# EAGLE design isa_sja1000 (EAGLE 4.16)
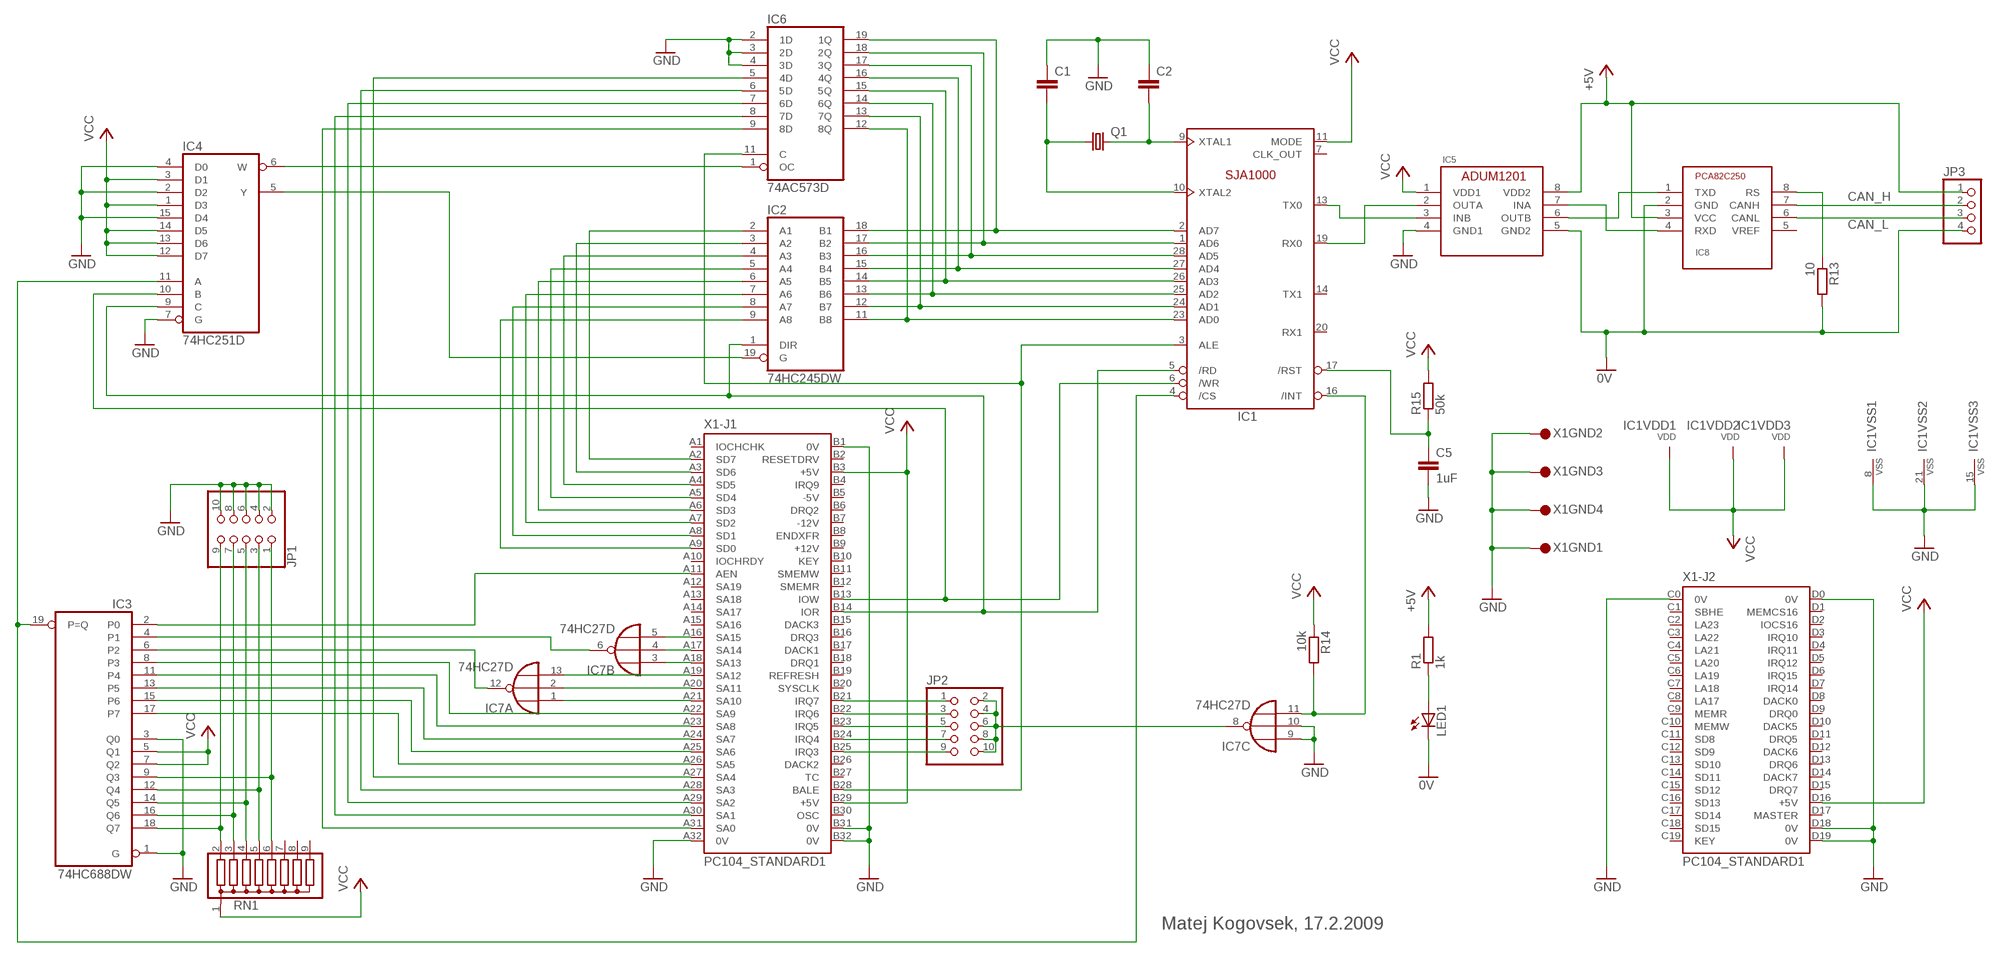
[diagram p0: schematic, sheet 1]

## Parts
C1  C-EUC0805  [C0805]
C2  C-EUC0805  [C0805]
C5  1uF  C-EUC1206  [C1206]
IC1  SJA1000T  [SO-28L]
IC2  74HC245DW  [SO20W]
IC3  74HC688DW  [SO20W]
IC4  74HC251D  [SO16]
IC5  ADUM1201  [SO08]
IC6  74AC573D  [SO20W]
IC7  74HC27D  [SO14]
IC8  MATEJ_PCA82C250  [MATEJ_SO8]
JP1  PINHD-2X5  [2X05]
JP2  PINHD-2X5  [2X05]
JP3  PINHD-1X4  [1X04]
LED1  LEDCHIPLED_1206  [CHIPLED_1206]
Q1  CRYSTALHC49S  [HC49/S]
R1  1k  R-EU_R1206  [R1206]
R13  10  R-EU_R1206  [R1206]
R14  10k  R-EU_R1206  [R1206]
R15  50k  R-EU_R1206  [R1206]
RN1  G08R  [SIL9]
X1  PC104_STANDARD1  [PC104-STANDARD]

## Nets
0V: IC5.5(GND2) IC8.2(GND) JP3.4 LED1.C R13.2
+5V: IC5.8(VDD2) IC8.3(VCC) JP3.1 R1.2
CAN_H: IC8.7(CANH) JP3.2
CAN_L: IC8.6(CANL) JP3.3
GND: C1.1 C2.1 C5.2 IC1.8(VSS) IC1.15(VSS) IC1.21(VSS) IC3.1(G) IC3.3(Q0) IC4.2(D2) IC4.4(D0) IC4.7(G) IC4.15(D4) IC5.4(GND1) IC6.2(1D) IC6.3(2D) IC6.4(3D) IC7.9(C:I0) IC7.10(C:I1) JP1.2 JP1.4 JP1.6 JP1.8 JP1.10 X1.A32(-J1:0V) X1.B1(-J1:0V) X1.B31(-J1:0V) X1.B32(-J1:0V) X1.C0(-J2:0V) X1.D0(-J2:0V) X1.D18(-J2:0V) X1.D19(-J2:0V) X1.GND@1 X1.GND@2 X1.GND@3 X1.GND@4
N$1: IC1.23(AD0) IC2.11(B8) IC6.12(8Q)
N$2: IC1.24(AD1) IC2.12(B7) IC6.13(7Q)
N$3: IC1.25(AD2) IC2.13(B6) IC6.14(6Q)
N$4: IC1.26(AD3) IC2.14(B5) IC6.15(5Q)
N$5: IC1.27(AD4) IC2.15(B4) IC6.16(4Q)
N$6: IC1.28(AD5) IC2.16(B3) IC6.17(3Q)
N$7: IC1.1(AD6) IC2.17(B2) IC6.18(2Q)
N$8: IC1.2(AD7) IC2.18(B1) IC6.19(1Q)
N$9: IC2.2(A1) X1.A2(-J1:SD7)
N$10: IC2.3(A2) X1.A3(-J1:SD6)
N$11: IC2.4(A3) X1.A4(-J1:SD5)
N$12: IC2.5(A4) X1.A5(-J1:SD4)
N$13: IC2.6(A5) X1.A6(-J1:SD3)
N$14: IC2.7(A6) X1.A7(-J1:SD2)
N$15: IC2.8(A7) X1.A8(-J1:SD1)
N$16: IC2.9(A8) X1.A9(-J1:SD0)
N$17: IC1.3(ALE) IC6.11(C) X1.B28(-J1:BALE)
N$18: IC1.6(/WR) IC4.10(B) X1.B13(-J1:IOW)
N$19: IC1.5(/RD) IC2.1(DIR) IC4.9(C) X1.B14(-J1:IOR)
N$20: IC3.11(P4) X1.A23(-J1:SA8)
N$21: IC7.1(A:I0) X1.A21(-J1:SA10)
N$22: IC6.9(8D) X1.A31(-J1:SA0)
N$23: IC6.8(7D) X1.A30(-J1:SA1)
N$24: IC6.7(6D) X1.A29(-J1:SA2)
N$25: IC6.6(5D) X1.A28(-J1:SA3)
N$26: IC6.5(4D) X1.A27(-J1:SA4)
N$27: IC3.17(P7) X1.A26(-J1:SA5)
N$28: IC3.15(P6) X1.A25(-J1:SA6)
N$29: IC3.13(P5) X1.A24(-J1:SA7)
N$30: IC2.19(G) IC4.5(Y)
N$31: IC4.6(W) IC6.1(OC)
N$32: IC3.8(P3) X1.A22(-J1:SA9)
N$33: JP2.9 X1.B25(-J1:IRQ3)
N$34: IC3.9(Q3) JP1.1 RN1.6
N$35: IC3.12(Q4) JP1.3 RN1.5
N$36: IC3.14(Q5) JP1.5 RN1.4
N$37: IC3.16(Q6) JP1.7 RN1.3
N$38: IC3.18(Q7) JP1.9 RN1.2
N$39: IC1.4(/CS) IC3.19(P=Q) IC4.11(A)
N$40: IC3.2(P0) X1.A11(-J1:AEN)
N$41: JP2.7 X1.B24(-J1:IRQ4)
N$42: JP2.5 X1.B23(-J1:IRQ5)
N$43: JP2.3 X1.B22(-J1:IRQ6)
N$44: JP2.1 X1.B21(-J1:IRQ7)
N$45: IC1.16(/INT) IC7.11(C:I2) R14.2
N$46: IC1.19(RX0) IC5.2(OUTA)
N$47: IC1.13(TX0) IC5.3(INB)
N$48: IC7.2(A:I1) X1.A20(-J1:SA11)
N$49: IC7.13(A:I2) X1.A19(-J1:SA12)
N$50: IC7.3(B:I0) X1.A18(-J1:SA13)
N$51: IC7.4(B:I1) X1.A17(-J1:SA14)
N$52: IC7.5(B:I2) X1.A16(-J1:SA15)
N$53: IC3.6(P2) IC7.12(A:O)
N$54: IC3.4(P1) IC7.6(B:O)
N$55: IC5.7(INA) IC8.4(RXD)
N$56: IC5.6(OUTB) IC8.1(TXD)
N$57: C5.1 IC1.17(/RST) R15.1
N$58: LED1.A R1.1
N$59: C1.2 IC1.10(XTAL2) Q1.1
N$60: C2.2 IC1.9(XTAL1) Q1.2
N$65: IC8.8(RS) R13.1
N$87: IC7.8(C:O) JP2.2 JP2.4 JP2.6 JP2.8 JP2.10
VCC: IC1.11(MODE) IC1.12(VDD) IC1.18(VDD) IC1.22(VDD) IC3.5(Q1) IC3.7(Q2) IC4.1(D3) IC4.3(D1) IC4.12(D7) IC4.13(D6) IC4.14(D5) IC5.1(VDD1) R14.1 R15.2 RN1.1 X1.B3(-J1:+5V) X1.B29(-J1:+5V) X1.D16(-J2:+5V)
Unconnected: IC1.7(CLK_OUT) IC1.14(TX1) IC1.20(RX1) IC8.5(VREF) RN1.7 RN1.8 RN1.9 X1.A1(-J1:IOCHCHK) X1.A10(-J1:IOCHRDY) X1.A12(-J1:SA19) X1.A13(-J1:SA18) X1.A14(-J1:SA17) X1.A15(-J1:SA16) X1.B2(-J1:RESETDRV) X1.B4(-J1:IRQ9) X1.B5(-J1:-5V) X1.B6(-J1:DRQ2) X1.B7(-J1:-12V) X1.B8(-J1:ENDXFR) X1.B9(-J1:+12V) X1.B10(-J1:KEY) X1.B11(-J1:SMEMW) X1.B12(-J1:SMEMR) X1.B15(-J1:DACK3) X1.B16(-J1:DRQ3) X1.B17(-J1:DACK1) X1.B18(-J1:DRQ1) X1.B19(-J1:REFRESH) X1.B20(-J1:SYSCLK) X1.B26(-J1:DACK2) X1.B27(-J1:TC) X1.B30(-J1:OSC) X1.C1(-J2:SBHE) X1.C2(-J2:LA23) X1.C3(-J2:LA22) X1.C4(-J2:LA21) X1.C5(-J2:LA20) X1.C6(-J2:LA19) X1.C7(-J2:LA18) X1.C8(-J2:LA17) X1.C9(-J2:MEMR) X1.C10(-J2:MEMW) X1.C11(-J2:SD8) X1.C12(-J2:SD9) X1.C13(-J2:SD10) X1.C14(-J2:SD11) X1.C15(-J2:SD12) X1.C16(-J2:SD13) X1.C17(-J2:SD14) X1.C18(-J2:SD15) X1.C19(-J2:KEY) X1.D1(-J2:MEMCS16) X1.D2(-J2:IOCS16) X1.D3(-J2:IRQ10) X1.D4(-J2:IRQ11) X1.D5(-J2:IRQ12) X1.D6(-J2:IRQ15) X1.D7(-J2:IRQ14) X1.D8(-J2:DACK0) X1.D9(-J2:DRQ0) X1.D10(-J2:DACK5) X1.D11(-J2:DRQ5) X1.D12(-J2:DACK6) X1.D13(-J2:DRQ6) X1.D14(-J2:DACK7) X1.D15(-J2:DRQ7) X1.D17(-J2:MASTER)

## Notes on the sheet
- SJA1000 | ADUM1201
- Matej Kogovsek, 17.2.2009

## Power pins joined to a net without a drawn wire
GND: IC2.10(GND) IC3.10(GND) IC4.8(GND) IC6.10(GND) IC7.7(P:GND)
VCC: IC2.20(VCC) IC3.20(VCC) IC4.16(VCC) IC6.20(VCC) IC7.14(P:VCC)

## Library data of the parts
C1 C2 C5 = rcl:C-EU: CAPACITOR, European symbol
IC1 = micro-philips:SJA1000: BASIC-CAN 2.0a Controller (former 82C200) Stand-alone CAN controller
IC2 = 74xx-eu:74*245: Octal BUS TRANSCEIVER, 3-state
IC3 = 74xx-eu:74*688: 8-bit MAGNITUDE/IDENTITY COMPARATOR, totem pole
IC4 = 74xx-eu:74*251: 1 of 8 data SELECTOR/MULTIPLEXER, 3-state
IC5 = matej_siwim:ADUM1201
IC6 = 74xx-eu:74*573: 8-bit D latch BUS DRIVER
IC7 = 74xx-eu:74*27: Triple 3-input NOR gate
IC8 = matej_siwim:MATEJ_PCA82C250: CAN controller interface
JP1 JP2 = pinhead:PINHD-2X5: PIN HEADER
JP3 = pinhead:PINHD-1X4: PIN HEADER
LED1 = led:LED: LED
Q1 = crystal:CRYSTAL: CRYSTAL
R1 R13-R15 = rcl:R-EU_: RESISTOR, European symbol
RN1 = resistor-sil:G08R: SIL RESISTOR
X1 = con-pc104:PC104_STANDARD: PC/104 Standard 16 bit

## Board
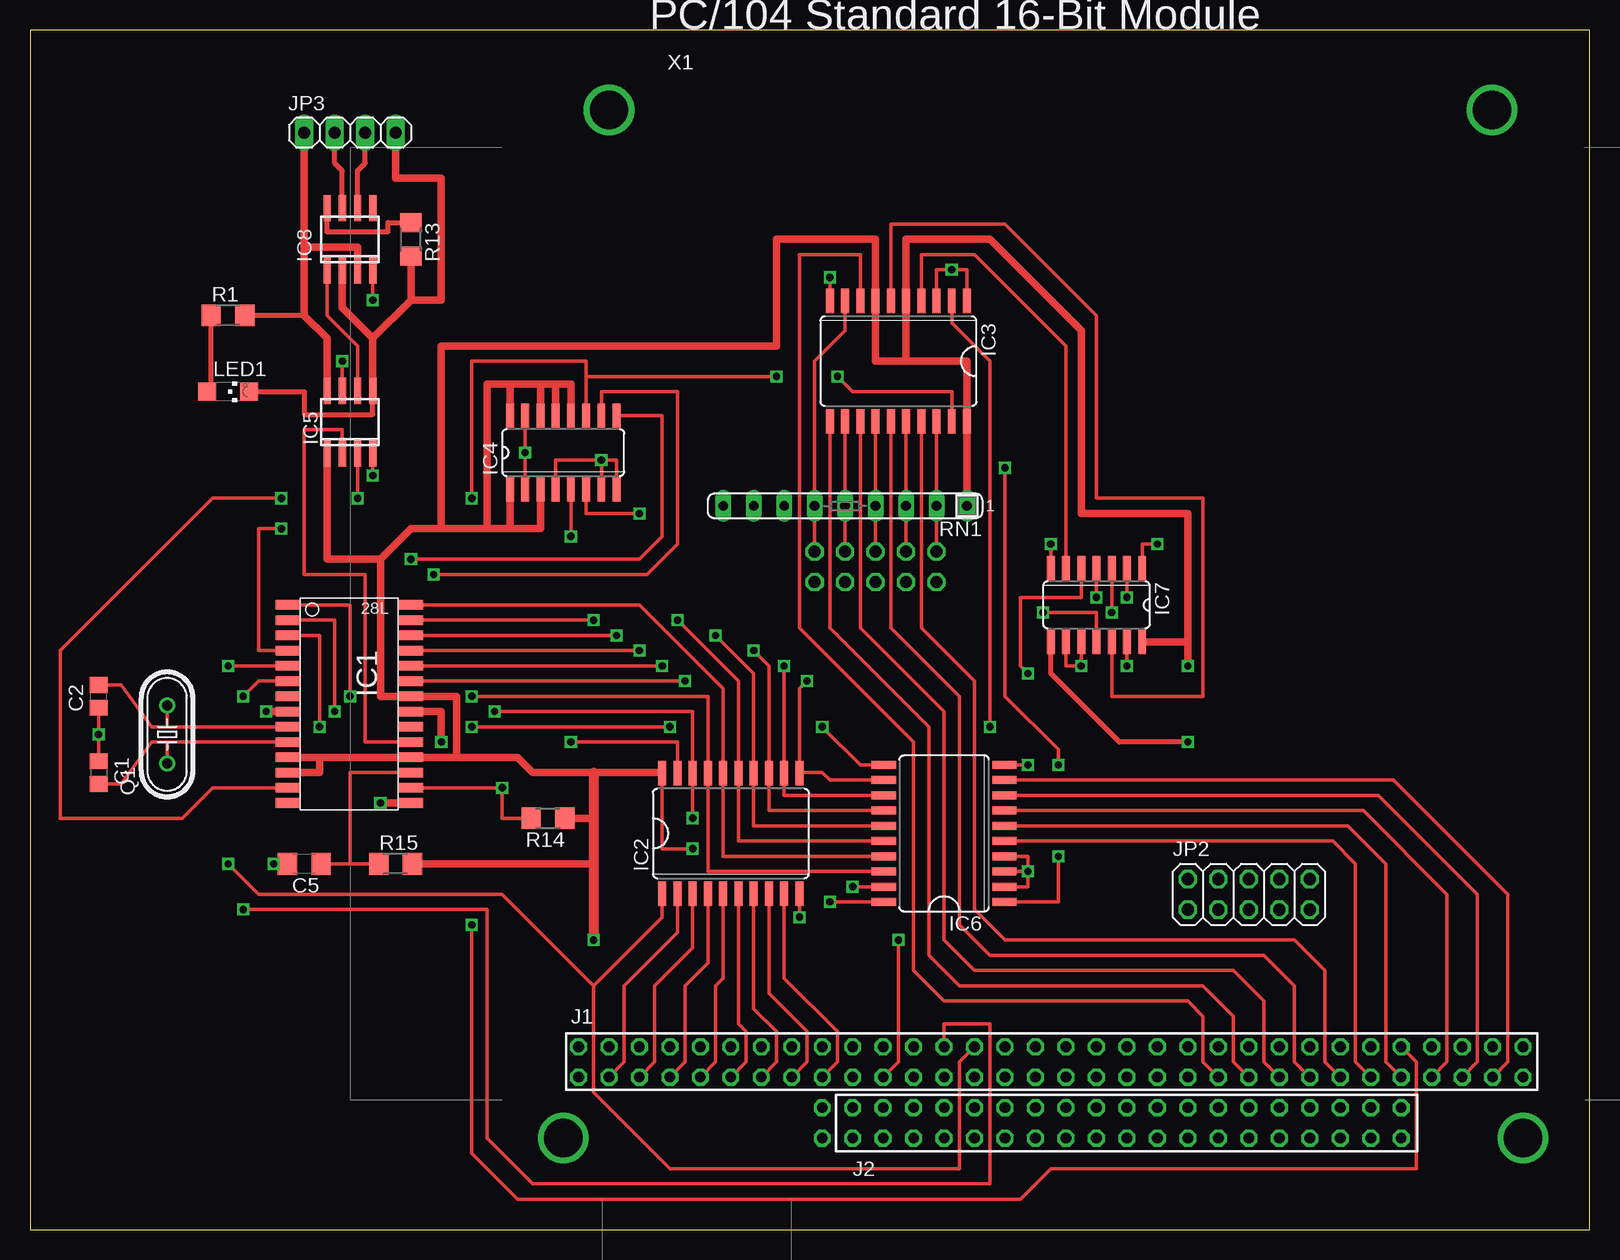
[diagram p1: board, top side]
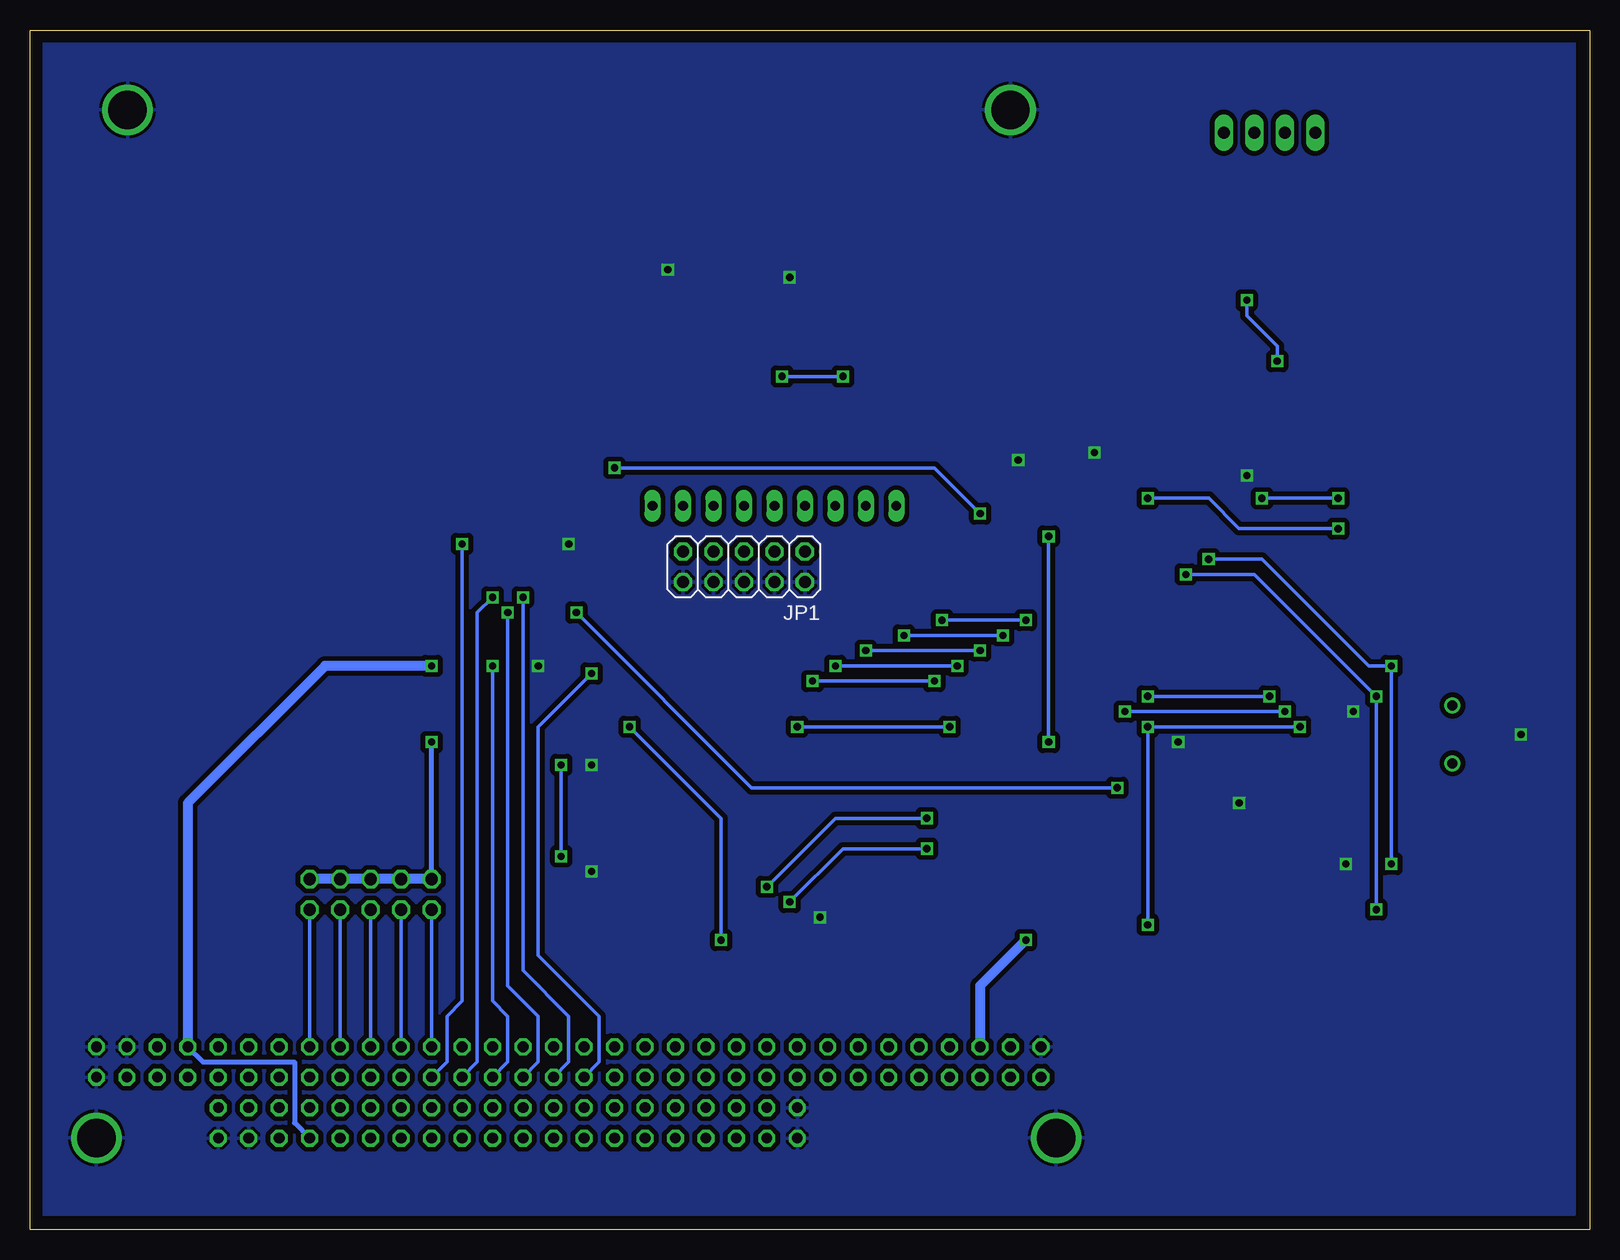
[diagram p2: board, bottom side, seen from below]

Size 130 x 100 mm. Coordinates in mm from the lower left corner, seen from the top.
Outline: 0,0 130,0 130,100 0,100 0,0
Copper layers (1*16): Top 0.035mm / dielectric 1.5mm / Bottom 0.035mm
Design rules "default": minimum track width 10mil, minimum drill 24mil, track to track 8mil, track to pad 8mil, pad to pad 8mil, via to via 8mil, smd to smd 8mil, copper to edge 40mil, drill to drill 8mil, minimum pad ring 10mil, minimum via ring 8mil, stop-mask expansion 4mil, vias tented up to drill 0mil, thermal gap 10mil

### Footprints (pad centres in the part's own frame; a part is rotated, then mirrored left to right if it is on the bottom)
C0805 = smd 1.3 x 1.5: 1 -0.95,0; 2 0.95,0
C1206 = smd 1.6 x 1.8: 1 -1.4,0; 2 1.4,0
SO-28L = smd 0.8 x 2: 1 -8.89,-5.207; 2 -7.62,-5.207; 3 -6.35,-5.207; 4 -5.08,-5.207; 5 -3.81,-5.207; 6 -2.54,-5.207; 7 -1.27,-5.207; 8 0,-5.207; 9 1.27,-5.207; 10 2.54,-5.207; 11 3.81,-5.207; 12 5.08,-5.207; 13 6.35,-5.207; 14 7.62,-5.207; 15 7.62,5.08; 16 6.35,5.08; 17 5.08,5.08; 18 3.81,5.08; 19 2.54,5.08; 20 1.27,5.08; 21 0,5.08; 22 -1.27,5.08; 23 -2.54,5.08; 24 -3.81,5.08; 25 -5.08,5.08; 26 -6.35,5.08; 27 -7.62,5.08; 28 -8.89,5.08
SO20W = smd 0.66 x 2.032: 1 -5.715,-5.029; 2 -4.445,-5.029; 3 -3.175,-5.029; 4 -1.905,-5.029; 5 -0.635,-5.029; 6 0.635,-5.029; 7 1.905,-5.029; 8 3.175,-5.029; 9 4.445,-5.029; 10 5.715,-5.029; 11 5.715,5.029; 12 4.445,5.029; 13 3.175,5.029; 14 1.905,5.029; 15 0.635,5.029; 16 -0.635,5.029; 17 -1.905,5.029; 18 -3.175,5.029; 19 -4.445,5.029; 20 -5.715,5.029
SO16 = smd 0.66 x 2.032: 1 -4.445,-3.073; 2 -3.175,-3.073; 3 -1.905,-3.073; 4 -0.635,-3.073; 5 0.635,-3.073; 6 1.905,-3.073; 7 3.175,-3.073; 8 4.445,-3.073; 9 4.445,3.073; 10 3.175,3.073; 11 1.905,3.073; 12 0.635,3.073; 13 -0.635,3.073; 14 -1.905,3.073; 15 -3.175,3.073; 16 -4.445,3.073
SO08@1 = smd 0.6 x 2.2: 1 -1.905,-2.6; 2 -0.635,-2.6; 3 0.635,-2.6; 4 1.905,-2.6; 5 1.905,2.6; 6 0.635,2.6; 7 -0.635,2.6; 8 -1.905,2.6
SO14 = smd 0.66 x 2.032: 1 -3.81,-3.073; 2 -2.54,-3.073; 3 -1.27,-3.073; 4 0,-3.073; 5 1.27,-3.073; 6 2.54,-3.073; 7 3.81,-3.073; 8 3.81,3.073; 9 2.54,3.073; 10 1.27,3.073; 11 0,3.073; 12 -1.27,3.073; 13 -2.54,3.073; 14 -3.81,3.073
MATEJ_SO8 = smd 0.6 x 2.2: 1 -1.905,-2.6; 2 -0.635,-2.6; 3 0.635,-2.6; 4 1.905,-2.6; 5 1.905,2.6; 6 0.635,2.6; 7 -0.635,2.6; 8 -1.905,2.6
2X05 = drill 1.016 octagon: 1 -5.08,-1.27; 2 -5.08,1.27; 3 -2.54,-1.27; 4 -2.54,1.27; 5 0,-1.27; 6 0,1.27; 7 2.54,-1.27; 8 2.54,1.27; 9 5.08,-1.27; 10 5.08,1.27
1X04 = drill 1.016 long: 1 -3.81,0; 2 -1.27,0; 3 1.27,0; 4 3.81,0
CHIPLED_1206 = smd 1.5 x 1.5: A 0,-1.75; C 0,1.75
HC49/S = drill 0.813 round: 1 -2.413,0; 2 2.413,0
R1206 = smd 1.6 x 1.8: 1 -1.4,0; 2 1.4,0
SIL9 = drill 0.813 long: 1 -10.16,0; 2 -7.62,0; 3 -5.08,0; 4 -2.54,0; 5 0,0; 6 2.54,0; 7 5.08,0; 8 7.62,0; 9 10.16,0
PC104-STANDARD = drill 0.9 pad 1.397 octagon: A1 6.35,10.16; A2 8.89,10.16; A3 11.43,10.16; A4 13.97,10.16; A5 16.51,10.16; A6 19.05,10.16; A7 21.59,10.16; A8 24.13,10.16; A9 26.67,10.16; A10 29.21,10.16; A11 31.75,10.16; A12 34.29,10.16; A13 36.83,10.16; A14 39.37,10.16; A15 41.91,10.16; A16 44.45,10.16; A17 46.99,10.16; A18 49.53,10.16; A19 52.07,10.16; A20 54.61,10.16; A21 57.15,10.16; A22 59.69,10.16; A23 62.23,10.16; A24 64.77,10.16; A25 67.31,10.16; A26 69.85,10.16; A27 72.39,10.16; A28 74.93,10.16; A29 77.47,10.16; A30 80.01,10.16; A31 82.55,10.16; A32 85.09,10.16; B1 6.35,12.7; B2 8.89,12.7; B3 11.43,12.7; B4 13.97,12.7; B5 16.51,12.7; B6 19.05,12.7; B7 21.59,12.7; B8 24.13,12.7; B9 26.67,12.7; B10 29.21,12.7; B11 31.75,12.7; B12 34.29,12.7; B13 36.83,12.7; B14 39.37,12.7; B15 41.91,12.7; B16 44.45,12.7; B17 46.99,12.7; B18 49.53,12.7; B19 52.07,12.7; B20 54.61,12.7; B21 57.15,12.7; B22 59.69,12.7; B23 62.23,12.7; B24 64.77,12.7; B25 67.31,12.7; B26 69.85,12.7; B27 72.39,12.7; B28 74.93,12.7; B29 77.47,12.7; B30 80.01,12.7; B31 82.55,12.7; B32 85.09,12.7; C0 26.67,7.62; C1 29.21,7.62; C2 31.75,7.62; C3 34.29,7.62; C4 36.83,7.62; C5 39.37,7.62; C6 41.91,7.62; C7 44.45,7.62; C8 46.99,7.62; C9 49.53,7.62; C10 52.07,7.62; C11 54.61,7.62; C12 57.15,7.62; C13 59.69,7.62; C14 62.23,7.62; C15 64.77,7.62; C16 67.31,7.62; C17 69.85,7.62; C18 72.39,7.62; C19 74.93,7.62; D0 26.67,5.08; D1 29.21,5.08; D2 31.75,5.08; D3 34.29,5.08; D4 36.83,5.08; D5 39.37,5.08; D6 41.91,5.08; D7 44.45,5.08; D8 46.99,5.08; D9 49.53,5.08; D10 52.07,5.08; D11 54.61,5.08; D12 57.15,5.08; D13 59.69,5.08; D14 62.23,5.08; D15 64.77,5.08; D16 67.31,5.08; D17 69.85,5.08; D18 72.39,5.08; D19 74.93,5.08 | drill 3.2 pad 4 round: GND@1 8.9,90.8; GND@2 82.5,90.8; GND@3 5.1,5.1; GND@4 85.1,5.1

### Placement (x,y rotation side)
C1  5.71,38.1 270 top
C2  5.71,44.45 90 top
C5  22.86,30.48 180 top
IC1  26.67,43.18 270 top
IC2  58.42,33.02 0 top
IC3  72.39,72.39 180 top
IC4  44.45,64.77 0 top
IC5  ADUM1201  [SO08@1]  26.67,67.31 0 top
IC6  76.2,33.02 90 top
IC7  88.9,52.07 180 top
IC8  26.67,82.55 0 top
JP1  70.48,55.24 180 bottom
JP2  101.6,27.94 0 top
JP3  26.67,91.44 0 top
LED1  16.51,69.85 270 top
Q1  11.43,41.27 90 top
R1  16.51,76.2 0 top
R13  31.75,82.55 270 top
R14  43.18,34.29 180 top
R15  30.48,30.48 0 top
RN1  67.94,60.33 180 top
X1  39.37,2.54 0 top

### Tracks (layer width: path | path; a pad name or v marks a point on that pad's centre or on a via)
0V
  Top 0.305: IC8.2 26.04,80.01
  Top 0.406: IC5.5 28.57,67.94 22.86,67.94 22.86,69.85 LED1.C
  Top 0.61: IC5.5 28.57,74.3 | 28.57,74.3 26.04,76.83 IC8.2 | 31.75,77.47 R13.2 | 28.57,74.3 31.75,77.47 | JP3.4 30.48,87.63 34.29,87.63 34.29,77.47 31.75,77.47
+5V
  Top 0.406: 22.86,76.2 R1.2
  Top 0.61: IC5.8 24.77,74.3 22.86,76.2 22.86,81.92 | 22.86,81.92 27.3,81.92 IC8.3 | 22.86,81.92 JP3.1
CAN_H
  Top 0.406: IC8.7 26.04,88.27 25.4,88.9 JP3.2
CAN_L
  Top 0.406: IC8.6 27.3,88.27 27.94,88.9 JP3.3
GND  (via drill 0.6)
  Top 0.305: v64.14,26.04 IC2.10 | IC4.15 v41.27,64.77 IC4.2 | IC4.8 48.9,64.14 v47.62,64.14 | v47.62,64.14 IC4.7 | IC4.4 43.81,64.14 v47.62,64.14 | C1.1 v5.71,41.27 C2.1 | IC7.9 86.36,46.99 v87.63,46.99 IC7.10 | IC7.7 v85.09,57.15 | IC6.2 83.19,28.57 v83.19,29.84 | IC6.4 83.19,31.11 v83.19,29.84 | IC6.3 v83.19,29.84 | IC6.10 v83.19,38.73 | IC3.3 75.56,80.01 v76.83,80.01 78.11,80.01 IC3.1 | IC3.10 v66.67,79.38 | v28.57,62.87 IC5.4 | 21.59,30.48 C5.2 v20.32,30.48
  Top 0.61: IC1.21 34.29,43.18 v34.29,40.64 | v29.21,35.56 IC1.15 | v19.68,43.18 IC1.8
  pour Bottom (isolate 0.406): 1.27,1.27 129.75,1.27 129.75,99.06 1.27,99.06
N$1  (via drill 0.6)
  Top 0.305: IC1.23 v54.61,45.72 | v64.77,45.72 64.14,45.09 IC2.11 64.14,38.1 66.04,38.1 66.67,37.47 IC6.12
  Bottom 0.305: v54.61,45.72 v64.77,45.72
N$2  (via drill 0.6)
  Top 0.305: IC1.24 v52.7,46.99 | v62.87,46.99 IC2.12 62.87,36.2 IC6.13
  Bottom 0.305: v52.7,46.99 v62.87,46.99
N$3  (via drill 0.6)
  Top 0.305: IC1.25 v50.8,48.26 | v60.33,48.26 61.59,46.99 IC2.13 61.59,34.92 IC6.14
  Bottom 0.305: v50.8,48.26 v60.33,48.26
N$4  (via drill 0.6)
  Top 0.305: IC1.26 v48.9,49.53 | v57.15,49.53 60.33,46.35 IC2.14 60.33,33.66 IC6.15
  Bottom 0.305: v48.9,49.53 v57.15,49.53
N$5  (via drill 0.6)
  Top 0.305: IC1.27 v46.99,50.8 | v53.98,50.8 59.05,45.72 IC2.15 59.05,32.38 IC6.16
  Bottom 0.305: v46.99,50.8 v53.98,50.8
N$6
  Top 0.305: IC1.28 50.8,52.07 57.78,45.09 IC2.16 57.78,31.11 IC6.17
N$7  (via drill 0.6)
  Top 0.305: IC6.18 56.52,29.84 IC2.17 56.52,44.45 v36.83,44.45 | IC1.1 26.67,52.07 v26.67,44.45
  Bottom 0.305: v26.67,44.45 v36.83,44.45
N$8  (via drill 0.6)
  Top 0.305: v68.58,28.57 IC6.19 | v55.24,34.29 IC2.18 55.24,43.18 v38.73,43.18 | IC1.2 25.4,50.8 v25.4,43.18
  Bottom 0.305: v68.58,28.57 62.87,34.29 v55.24,34.29 | v25.4,43.18 v38.73,43.18
N$9
  Top 0.305: IC2.2 53.98,24.77 49.53,20.32 49.53,13.97 X1.A2
N$10
  Top 0.305: X1.A3 52.07,13.97 52.07,20.32 55.24,23.5 IC2.3
N$11
  Top 0.305: IC2.4 56.52,22.23 54.61,20.32 54.61,13.97 X1.A4
N$12
  Top 0.305: IC2.5 57.78,20.95 57.15,20.32 57.15,13.97 X1.A5
N$13
  Top 0.305: IC2.6 59.05,17.14 59.69,16.51 59.69,13.97 X1.A6
N$14
  Top 0.305: IC2.7 60.33,18.41 62.23,16.51 62.23,13.97 X1.A7
N$15
  Top 0.305: IC2.8 61.59,19.68 64.77,16.51 64.77,13.97 X1.A8
N$16
  Top 0.305: IC2.9 62.87,20.95 67.31,16.51 67.31,13.97 X1.A9
N$17  (via drill 0.6)
  Top 0.305: IC1.3 24.13,49.53 v24.13,41.91 | v36.83,41.91 v53.34,41.91 | v66.04,41.91 69.22,38.73 IC6.11 | X1.B28 115.57,13.97 115.57,5.08 85.09,5.08 82.55,2.54 40.64,2.54 36.83,6.35 v36.83,25.4
  Bottom 0.305: v24.13,41.91 v36.83,41.91 v36.83,25.4 | v53.34,41.91 v66.04,41.91
N$18  (via drill 0.6)
  Top 0.305: X1.B13 76.2,17.14 80.01,17.14 80.01,3.81 41.91,3.81 38.1,7.62 38.1,26.67 v17.78,26.67 | v17.78,44.45 19.05,45.72 IC1.6 | IC4.10 47.62,69.85 53.98,69.85 53.98,57.15 51.44,54.61 v33.66,54.61
  Bottom 0.305: v17.78,26.67 v17.78,44.45 27.94,54.61 v33.66,54.61
N$19  (via drill 0.6)
  Top 0.305: X1.B14 77.47,13.97 77.47,5.08 53.34,5.08 46.99,11.43 46.99,20.32 | 46.99,20.32 52.7,26.04 IC2.1 | v16.51,46.99 IC1.5 | v16.51,30.48 19.05,27.94 39.37,27.94 46.99,20.32 | IC4.9 52.7,67.84 52.7,57.78 50.8,55.88 v31.75,55.88
  Bottom 0.305: v16.51,30.48 v16.51,46.99 18.41,46.99 27.3,55.88 v31.75,55.88
N$20
  Top 0.305: X1.A23 100.33,13.97 100.33,17.78 97.79,20.32 77.47,20.32 74.93,22.86 74.93,41.91 66.67,50.16 IC3.11
N$21  (via drill 0.6)
  Top 0.305: v93.98,57.15 92.71,57.15 IC7.1
  Bottom 0.305: X1.A21 95.25,13.97 95.25,17.78 93.98,19.05 v93.98,57.15
N$22
  Top 0.305: IC6.9 113.67,37.47 123.19,27.94 123.19,13.97 X1.A31
N$23
  Top 0.305: IC6.8 112.39,36.2 120.65,27.94 120.65,13.97 X1.A30
N$24
  Top 0.305: IC6.7 111.12,34.92 118.11,27.94 118.11,13.97 X1.A29
N$25
  Top 0.305: IC6.6 109.86,33.66 113.03,30.48 113.03,13.97 X1.A28
N$26
  Top 0.305: IC6.5 108.58,32.38 110.49,30.48 110.49,13.97 X1.A27
N$27
  Top 0.305: X1.A26 107.95,13.97 107.95,21.59 105.41,24.13 81.28,24.13 78.74,26.67 78.74,45.72 74.3,50.16 IC3.17
N$28
  Top 0.305: X1.A25 105.41,13.97 105.41,20.32 102.87,22.86 80.01,22.86 77.47,25.4 77.47,44.45 71.75,50.16 IC3.15
N$29
  Top 0.305: X1.A24 102.87,13.97 102.87,19.05 100.33,21.59 78.74,21.59 76.2,24.13 76.2,43.18 69.22,50.16 IC3.13
N$30  (via drill 0.6)
  Top 0.305: IC2.19 53.98,40.64 v45.09,40.64 | v45.09,57.78 IC4.5
  Bottom 0.305: v45.09,40.64 v45.09,57.78
N$31  (via drill 0.6)
  Top 0.305: IC6.1 85.72,27.3 v85.72,31.11 | v85.72,38.73 85.72,40.01 81.28,44.45 v81.28,63.5 | v50.8,59.69 46.35,59.69 IC4.6
  Bottom 0.305: v85.72,31.11 v85.72,38.73 | v81.28,63.5 54.61,63.5 v50.8,59.69
N$32
  Top 0.305: X1.A22 97.79,13.97 97.79,17.78 96.52,19.05 76.2,19.05 73.66,21.59 73.66,40.64 64.14,50.16 64.14,81.28 69.22,81.28 IC3.8
N$33
  Bottom 0.305: X1.B25 JP2.9
N$34
  Top 0.305: 67.94,77.47 IC3.9 67.94,74.93 65.41,72.39 RN1.6 JP1.1
N$35
  Top 0.305: IC3.12 RN1.5 JP1.3
N$36
  Top 0.305: IC3.14 RN1.4 JP1.5
N$37
  Top 0.305: IC3.16 RN1.3 JP1.7
N$38
  Top 0.305: JP1.9 RN1.2 IC3.18
N$39  (via drill 0.6)
  Top 0.305: IC1.4 19.05,48.26 19.05,58.42 v20.95,58.42 | v36.83,60.96 36.83,72.39 46.35,72.39 46.35,71.12 | 46.35,71.12 IC4.11 | IC3.19 76.83,69.85 68.58,69.85 v67.31,71.12 | 46.35,71.12 v62.23,71.12
  Bottom 0.305: v20.95,58.42 29.21,58.42 31.75,60.96 v36.83,60.96 | v62.23,71.12 v67.31,71.12
N$40  (via drill 0.6)
  Top 0.305: IC3.2 76.83,75.56 80.01,72.39 v80.01,41.91 | v72.39,24.13 72.39,13.97 X1.A11
  Bottom 0.305: v80.01,41.91 72.39,34.29 v72.39,24.13
N$41
  Bottom 0.305: X1.B24 JP2.7
N$42
  Bottom 0.305: X1.B23 JP2.5
N$43
  Bottom 0.305: X1.B22 JP2.3
N$44
  Bottom 0.305: X1.B21 JP2.1
N$45  (via drill 0.6)
  Top 0.305: IC7.11 88.9,51.44 v84.45,51.44 | IC1.16 v39.37,36.83 39.37,34.29 R14.2
  Bottom 0.305: v84.45,51.44 69.85,36.83 v39.37,36.83
N$46
  Top 0.305: IC1.19 27.94,40.64 27.94,54.61 22.86,54.61 22.86,66.67 26.04,66.67 IC5.2
N$47  (via drill 0.6)
  Top 0.305: IC1.13 15.24,36.83 12.7,34.29 2.54,34.29 2.54,48.26 15.24,60.96 v20.95,60.96 | v27.3,60.96 IC5.3
  Top 0.406: IC5.3 27.3,64.77
  Bottom 0.305: v20.95,60.96 v27.3,60.96
N$48  (via drill 0.6)
  Top 0.305: 91.44,55.24 IC7.2 v91.44,52.7
  Bottom 0.305: X1.A20 92.71,13.97 92.71,51.44 v91.44,52.7
N$49  (via drill 0.6)
  Top 0.305: v91.44,46.99 IC7.13
  Bottom 0.305: X1.A19 90.17,13.97 90.17,17.78 91.44,19.05 v91.44,46.99
N$50  (via drill 0.6)
  Top 0.305: 90.17,55.24 IC7.3 v90.17,51.44
  Bottom 0.305: X1.A18 87.63,13.97 87.63,17.78 90.17,20.32 v90.17,51.44
N$51  (via drill 0.6)
  Top 0.305: 88.9,55.24 IC7.4 v88.9,52.7
  Bottom 0.305: X1.A17 85.09,13.97 85.09,17.78 88.9,21.59 v88.9,52.7
N$52  (via drill 0.6)
  Top 0.305: v83.19,46.35 82.55,46.99 82.55,52.7 87.63,52.7 IC7.5 87.63,55.24
  Bottom 0.305: X1.A16 82.55,13.97 82.55,17.78 87.63,22.86 87.63,41.91 v83.19,46.35
N$53
  Top 0.305: IC3.6 71.75,83.82 81.28,83.82 88.9,76.2 88.9,60.96 97.79,60.96 97.79,44.45 90.17,44.45 IC7.12
N$54
  Top 0.305: IC7.6 86.36,73.66 78.74,81.28 74.3,81.28 IC3.4
N$55  (via drill 0.6)
  Top 0.305: IC5.7 v26.04,72.39 | 28.57,80.01 IC8.4 v28.57,77.47
  Bottom 0.305: v26.04,72.39 26.04,73.66 28.57,76.2 v28.57,77.47
N$56
  Top 0.305: IC5.6 27.3,73.66 24.77,76.2 IC8.1 24.77,80.01
N$57
  Top 0.305: IC1.17 26.67,38.1 26.67,30.48 | 29.21,30.48 R15.1 26.67,30.48 | C5.1 26.67,30.48
N$58
  Top 0.406: 14.61,69.85 LED1.A 15.11,69.85 R1.1
N$59
  Top 0.305: 11.43,40.64 10.16,40.64 7.62,37.15 C1.2 | 11.43,40.64 IC1.10 | 11.43,40.64 Q1.1
N$60
  Top 0.305: 11.43,41.91 10.16,41.91 7.62,45.4 C2.2 | 11.43,41.91 IC1.9 | 11.43,41.91 Q1.2
N$65
  Top 0.406: IC8.8 24.77,83.19 29.84,83.19 29.84,83.95 R13.1
N$87  (via drill 0.6)
  Top 0.406: IC7.8 85.09,46.35 90.81,40.64 v96.52,40.64
  Bottom 0.406: JP2.2 v96.52,40.64
  Bottom 0.813: JP2.10 JP2.8 JP2.6 JP2.4 JP2.2
VCC  (via drill 0.6)
  Top 0.305: IC4.3 42.55,61.59 | 78.11,67.31 IC3.20 | IC2.20 52.7,31.75 v55.24,31.75 | v66.67,27.3 IC6.20
  Top 0.406: 52.7,38.1 IC2.20 | IC5.1 24.77,64.77
  Top 0.61: RN1.1 78.11,67.31 78.11,72.39 73.03,72.39 | 40.01,70.48 IC4.16 | 40.01,70.48 42.55,70.48 | 42.55,70.48 IC4.14 | IC4.12 45.09,70.48 43.81,70.48 | 42.55,70.48 43.81,70.48 | 43.81,70.48 IC4.13 | 24.13,39.37 IC1.11 | 24.13,39.37 24.13,38.1 IC1.12 | 35.56,39.37 35.56,44.45 IC1.22 29.21,44.45 29.21,55.88 | 35.56,39.37 40.64,39.37 41.91,38.1 46.99,38.1 52.7,38.1 | 29.21,55.88 24.77,55.88 IC5.1 | IC4.3 42.55,58.42 40.01,58.42 | 40.01,58.42 IC4.1 | 73.03,72.39 IC3.5 73.03,82.55 80.01,82.55 87.63,74.93 87.63,59.69 96.52,59.69 96.52,49 | 73.03,72.39 70.48,72.39 IC3.7 70.48,82.55 62.23,82.55 62.23,73.66 34.29,73.66 34.29,58.42 | 96.52,49 IC7.14 | 29.21,55.88 31.75,58.42 34.29,58.42 | 34.29,58.42 38.1,58.42 | 38.1,58.42 38.1,70.48 40.01,70.48 | 38.1,58.42 40.01,58.42 | 96.52,49 v96.52,46.99 | 24.13,39.37 IC1.18 35.56,39.37 | 46.99,30.48 R15.2 | 46.99,34.29 R14.1
  Top 0.813: 46.99,38.1 46.99,34.29 46.99,30.48 v46.99,24.13
  Bottom 0.305: v55.24,31.75 62.23,31.75 v66.67,27.3
  Bottom 0.406: X1.D16 107.95,8.89 107.95,13.97 115.57,13.97 X1.B29
  Bottom 0.813: X1.B3 50.8,20.32 v46.99,24.13 | X1.B29 116.84,35.56 105.41,46.99 v96.52,46.99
